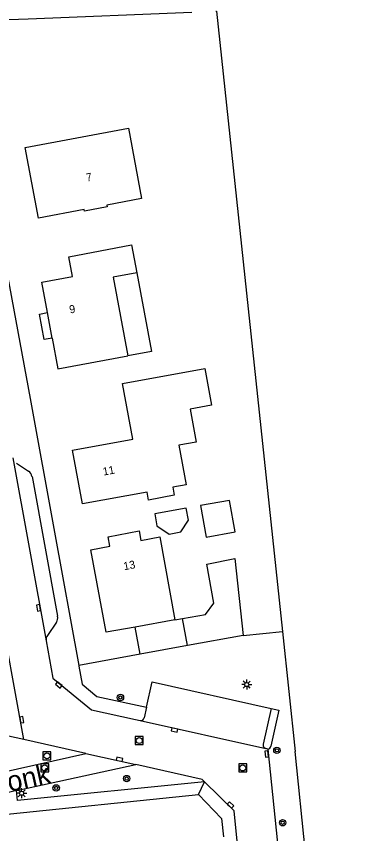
# Model space of a CAD drawing. Extents: x 140000 to 143000, y 403500 to 406000.
# Drawn here: x 140728.3 to 140772.9, y 403992.2 to 404094.4 of the extents above; entities that cross this region are included whole.
import ezdxf

# ---------------------------------------------------------------- set-up
doc = ezdxf.new("R2010")
doc.units = 0
for name, color, linetype in [('gg-afsc-erfafscheiding', 7, 'Continuous'), ('gg-afsc-hekwerk', 7, 'Continuous'), ('gg-anno-huisnummerreeks BGT', 7, 'Continuous'), ('gg-anno-openbare ruimte label', 7, 'Continuous'), ('gg-bbg-bijgebouw', 7, 'Continuous'), ('gg-bbg-gedigitaliseerde bijgebouw', 7, 'Continuous'), ('gg-bbg-hoofdgebouw', 7, 'Continuous'), ('gg-bbg-luifel en loopbrug', 7, 'Continuous'), ('gg-knt-verharding', 7, 'Continuous'), ('gt-grn-weggrens', 7, 'Continuous'), ('gt-symb-boom', 7, 'Continuous'), ('gt-symb-kolk', 7, 'Continuous'), ('gt-symb-lichtmast', 7, 'Continuous'), ('gt-symb-rioolschacht', 7, 'Continuous')]:
    doc.layers.add(name, color=color, linetype=linetype)

# ---------------------------------------------------------------- blocks, each defined once
blk = doc.blocks.new('gt0-KOLK')
at = {"layer": 'gt-symb-kolk'}
blk.add_lwpolyline([(0, 0), (0.38, 0), (0.38, 0.4), (-0.37, 0.4), (-0.37, 0), (0, 0)], dxfattribs=at)
blk = doc.blocks.new('gt0-LMAST')
at = {"layer": 'gt-symb-lichtmast'}
for p, q in [((-0.18, 0.17), (-0.45, 0.44)), ((-0.01, 0.25), (-0.01, 0.62)), ((0.17, 0.17), (0.44, 0.44)), ((-0.26, 0), (-0.63, 0)), ((-0.18, -0.18), (-0.45, -0.45)), ((-0.01, -0.25), (-0.01, -0.63)), ((0.44, -0.45), (0.17, -0.18)), ((0.24, 0), (0.62, 0))]:
    blk.add_line(p, q, dxfattribs=at)
blk.add_circle((-0.01, 0), 0.25, dxfattribs=at)
blk = doc.blocks.new('gt0-BOOM')
at = {"layer": 'gt-symb-boom'}
for radius in [0.4, 0.2]:
    blk.add_circle((0, 0), radius, dxfattribs=at)
blk = doc.blocks.new('gt0-RS')
at = {"layer": 'gt-symb-rioolschacht'}
blk.add_lwpolyline([(-0.5, -0.5), (0.5, -0.5), (0.5, 0.5), (-0.5, 0.5)], close=True, dxfattribs=at)
blk.add_circle((0, 0), 0.375, dxfattribs=at)

msp = doc.modelspace()

# ---------------------------------------------------------------- linework, layer by layer
at = {"layer": 'gg-afsc-erfafscheiding'}
msp.add_lwpolyline([(140723.62, 404093.86), (140729.73, 404094.08), (140750.18, 404094.89)], dxfattribs=at)
at = {"layer": 'gg-afsc-hekwerk'}
for p, q in [((140756.62, 404016.99), (140761.53, 404017.51)), ((140761.53, 404017.51), (140763.13, 404002.49)), ((140772.92, 403904.84), (140763.13, 404002.49))]:
    msp.add_line(p, q, dxfattribs=at)
for points in [[(140723.62, 404093.86), (140729.73, 404094.08), (140750.18, 404094.89)], [(140753.21, 404095.01), (140753.3, 404095.01), (140761.53, 404017.51)]]:
    msp.add_lwpolyline(points, dxfattribs=at)
at = {"layer": 'gg-bbg-bijgebouw'}
msp.add_lwpolyline([(140751.91, 404019.63), (140752.94, 404021.04), (140752.08, 404025.9), (140755.58, 404026.61), (140756.62, 404016.99)], dxfattribs=at)
at = {"layer": 'gg-bbg-gedigitaliseerde bijgebouw'}
for p, q in [((140749.05, 404019.12), (140751.91, 404019.63)), ((140749.66, 404015.74), (140749.05, 404019.12)), ((140756.62, 404016.99), (140749.66, 404015.74))]:
    msp.add_line(p, q, dxfattribs=at)
at = {"layer": 'gg-bbg-hoofdgebouw'}
for p, q in [((140732.74, 404054.16), (140732.15, 404057.35)), ((140748.08, 404018.95), (140743.12, 404018.05))]:
    msp.add_line(p, q, dxfattribs=at)
for points in [[(140743.93, 404071.59), (140739.57, 404070.77), (140739.61, 404070.56), (140736.78, 404070.03), (140736.74, 404070.24), (140731.03, 404069.17), (140729.38, 404077.97), (140742.28, 404080.39), (140743.93, 404071.59)], [(140732.15, 404057.35), (140731.45, 404061.14), (140735.27, 404061.86), (140734.81, 404064.31), (140742.68, 404065.8), (140743.32, 404062.33)], [(140743.32, 404062.33), (140740.37, 404061.79), (140742.19, 404051.95)], [(140732.74, 404054.16), (140733.45, 404050.34), (140742.19, 404051.95)], [(140741.55, 404048.49), (140751.81, 404050.38), (140752.66, 404045.78), (140750, 404045.3), (140750.76, 404041.17), (140748.59, 404040.76), (140749.51, 404035.82), (140747.82, 404035.51), (140748, 404034.51), (140744.78, 404033.91), (140744.6, 404034.91), (140736.53, 404033.45), (140735.29, 404040.15), (140742.82, 404041.53), (140741.55, 404048.49)], [(140743.12, 404018.05), (140739.48, 404017.4), (140737.58, 404027.7), (140739.96, 404028.15), (140739.74, 404029.34), (140743.61, 404030.07), (140743.84, 404028.88), (140746.21, 404029.32), (140748.08, 404018.95)]]:
    msp.add_lwpolyline(points, dxfattribs=at)
at = {"layer": 'gg-bbg-luifel en loopbrug'}
for p, q in [((140748.08, 404018.95), (140749.05, 404019.12)), ((140743.76, 404014.66), (140743.12, 404018.05)), ((140749.66, 404015.74), (140743.76, 404014.66))]:
    msp.add_line(p, q, dxfattribs=at)
for points in [[(140743.32, 404062.33), (140745.14, 404052.5), (140742.19, 404051.95)], [(140732.74, 404054.16), (140731.76, 404053.99), (140731.18, 404057.17), (140732.15, 404057.35)], [(140745.84, 404030.7), (140747.35, 404029.66), (140748.83, 404029.93), (140749.77, 404031.42), (140749.5, 404032.9), (140745.57, 404032.18), (140745.84, 404030.7)], [(140754.91, 404033.88), (140751.27, 404033.22), (140751.99, 404029.29), (140755.63, 404029.95), (140754.91, 404033.88)]]:
    msp.add_lwpolyline(points, dxfattribs=at)
at = {"layer": 'gg-knt-verharding'}
for p, q in [((140727.84, 404039.21), (140731.99, 404016.33)), ((140728.27, 404038.55), (140729.8, 404037.54)), ((140730.23, 404036.88), (140733.42, 404019.39)), ((140729.2, 404003.99), (140725.41, 404024.83)), ((140733.27, 404018.65), (140732.15, 404017.01)), ((140743.76, 404014.66), (140736.07, 404013.25)), ((140744.54, 404008.02), (140744.24, 404006.69)), ((140760.12, 404007.87), (140759.11, 404003.39)), ((140743.74, 404006.35), (140759.44, 404002.86)), ((140736.95, 404002.25), (140729.2, 404003.99)), ((140726.39, 403999.86), (140736.95, 404002.25)), ((140736.95, 404002.25), (140743.19, 404000.85)), ((140759.69, 404002.8), (140759.44, 404002.86)), ((140759.69, 404002.8), (140761.63, 403983.97)), ((140728.3, 403997.6), (140743.19, 404000.85)), ((140728.3, 403997.6), (140726.79, 403997.26)), ((140720.04, 403993.94), (140751.03, 403997.1))]:
    msp.add_line(p, q, dxfattribs=at)
for points in [[(140724.09, 404063.79), (140726.81, 404063.93), (140726.93, 404063.32), (140729.98, 404046.6), (140733.03, 404029.89), (140736.07, 404013.25)], [(140729.2, 404003.99), (140727.29, 404004.42), (140724.08, 404022.03)], [(140731.99, 404016.33), (140732.83, 404011.66), (140737.68, 404007.72), (140743.17, 404006.48), (140743.74, 404006.35)], [(140736.07, 404013.25), (140736.08, 404013.17), (140736.49, 404010.91), (140738.34, 404009.38), (140744.54, 404008.02)], [(140744.54, 404008.02), (140745.23, 404011.19), (140760.12, 404007.87)], [(140760.12, 404007.87), (140761.09, 404007.65), (140760.08, 404003.17)], [(140751.79, 403998.71), (140751.49, 403998.99), (140743.19, 404000.85)], [(140751.79, 403998.71), (140728.43, 403996.35), (140728.3, 403997.6)], [(140760.24, 403915.9), (140760.46, 403944.96), (140755.49, 403995.09), (140751.79, 403998.71)], [(140751.03, 403997.1), (140753.91, 403994.11), (140754.15, 403991.81)]]:
    msp.add_lwpolyline(points, dxfattribs=at)
for centre, radius, start, end in [((140729.24, 404036.7), 1, 10.4223, 56.3075), ((140732.44, 404019.21), 1, 325.8708, 10.3519), ((140732.98, 404016.45), 0.998, 145.8493, 186.8726), ((140743.81, 404006.79), 0.442, 260.5061, 347.5521), ((140759.56, 404003.3), 0.458, 168.0582, 255.145), ((140759.66, 404003.23), 0.428, 274.2849, 352.562)]:
    msp.add_arc(centre, radius, start, end, dxfattribs=at)
at = {"layer": 'gt-grn-weggrens'}
msp.add_line((140751.03, 403997.1), (140751.79, 403998.71), dxfattribs=at)

# ---------------------------------------------------------------- block references
at = {"layer": 'gt-symb-boom'}
for p in [(140741.28, 404009.24), (140760.83, 404002.64), (140742.06, 403999.11), (140733.25, 403997.94), (140761.55, 403993.59)]:
    msp.add_blockref('gt0-BOOM', p, dxfattribs=at)
at = {"layer": 'gt-symb-kolk'}
for p, rotation in [((140731.24, 404020.48), 100.27958378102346), ((140733.7, 404010.96), 140.84233083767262), ((140728.76, 404006.43), -79.6872135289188), ((140748.09, 404005.38), 167.4475583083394), ((140759.75, 404002.2), 95.87680238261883), ((140741.11, 404001.32), -12.63471961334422), ((140754.89, 403995.67), -44.31522249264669)]:
    msp.add_blockref('gt0-KOLK', p, dxfattribs=dict(at, rotation=rotation))
at = {"layer": 'gt-symb-lichtmast'}
for p in [(140757.07, 404010.86), (140728.94, 403997.27)]:
    msp.add_blockref('gt0-LMAST', p, dxfattribs=at)
at = {"layer": 'gt-symb-rioolschacht'}
for p in [(140743.63, 404003.86), (140732.09, 404001.95), (140731.82, 404000.44), (140756.56, 404000.44)]:
    msp.add_blockref('gt0-RS', p, dxfattribs=at)

# ---------------------------------------------------------------- texts
at = {"layer": 'gg-anno-huisnummerreeks BGT'}
for s, rotation, p in [('7', 10.4, (140737.07, 404073.72)), ('9', 10.6, (140734.98, 404057.23)), ('11', 10.5, (140739.16, 404036.97)), ('13', 10.6, (140741.74, 404025.14))]:
    msp.add_text(s, height=1, rotation=rotation, dxfattribs=at).set_placement(p)
at = {"layer": 'gg-anno-openbare ruimte label'}
msp.add_text('Vriesdonk', height=2.5, rotation=12.4, dxfattribs=at).set_placement((140718.15, 403995.41))

doc.saveas('drawing.dxf')
